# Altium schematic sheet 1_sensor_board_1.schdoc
size 353 x 259 mm
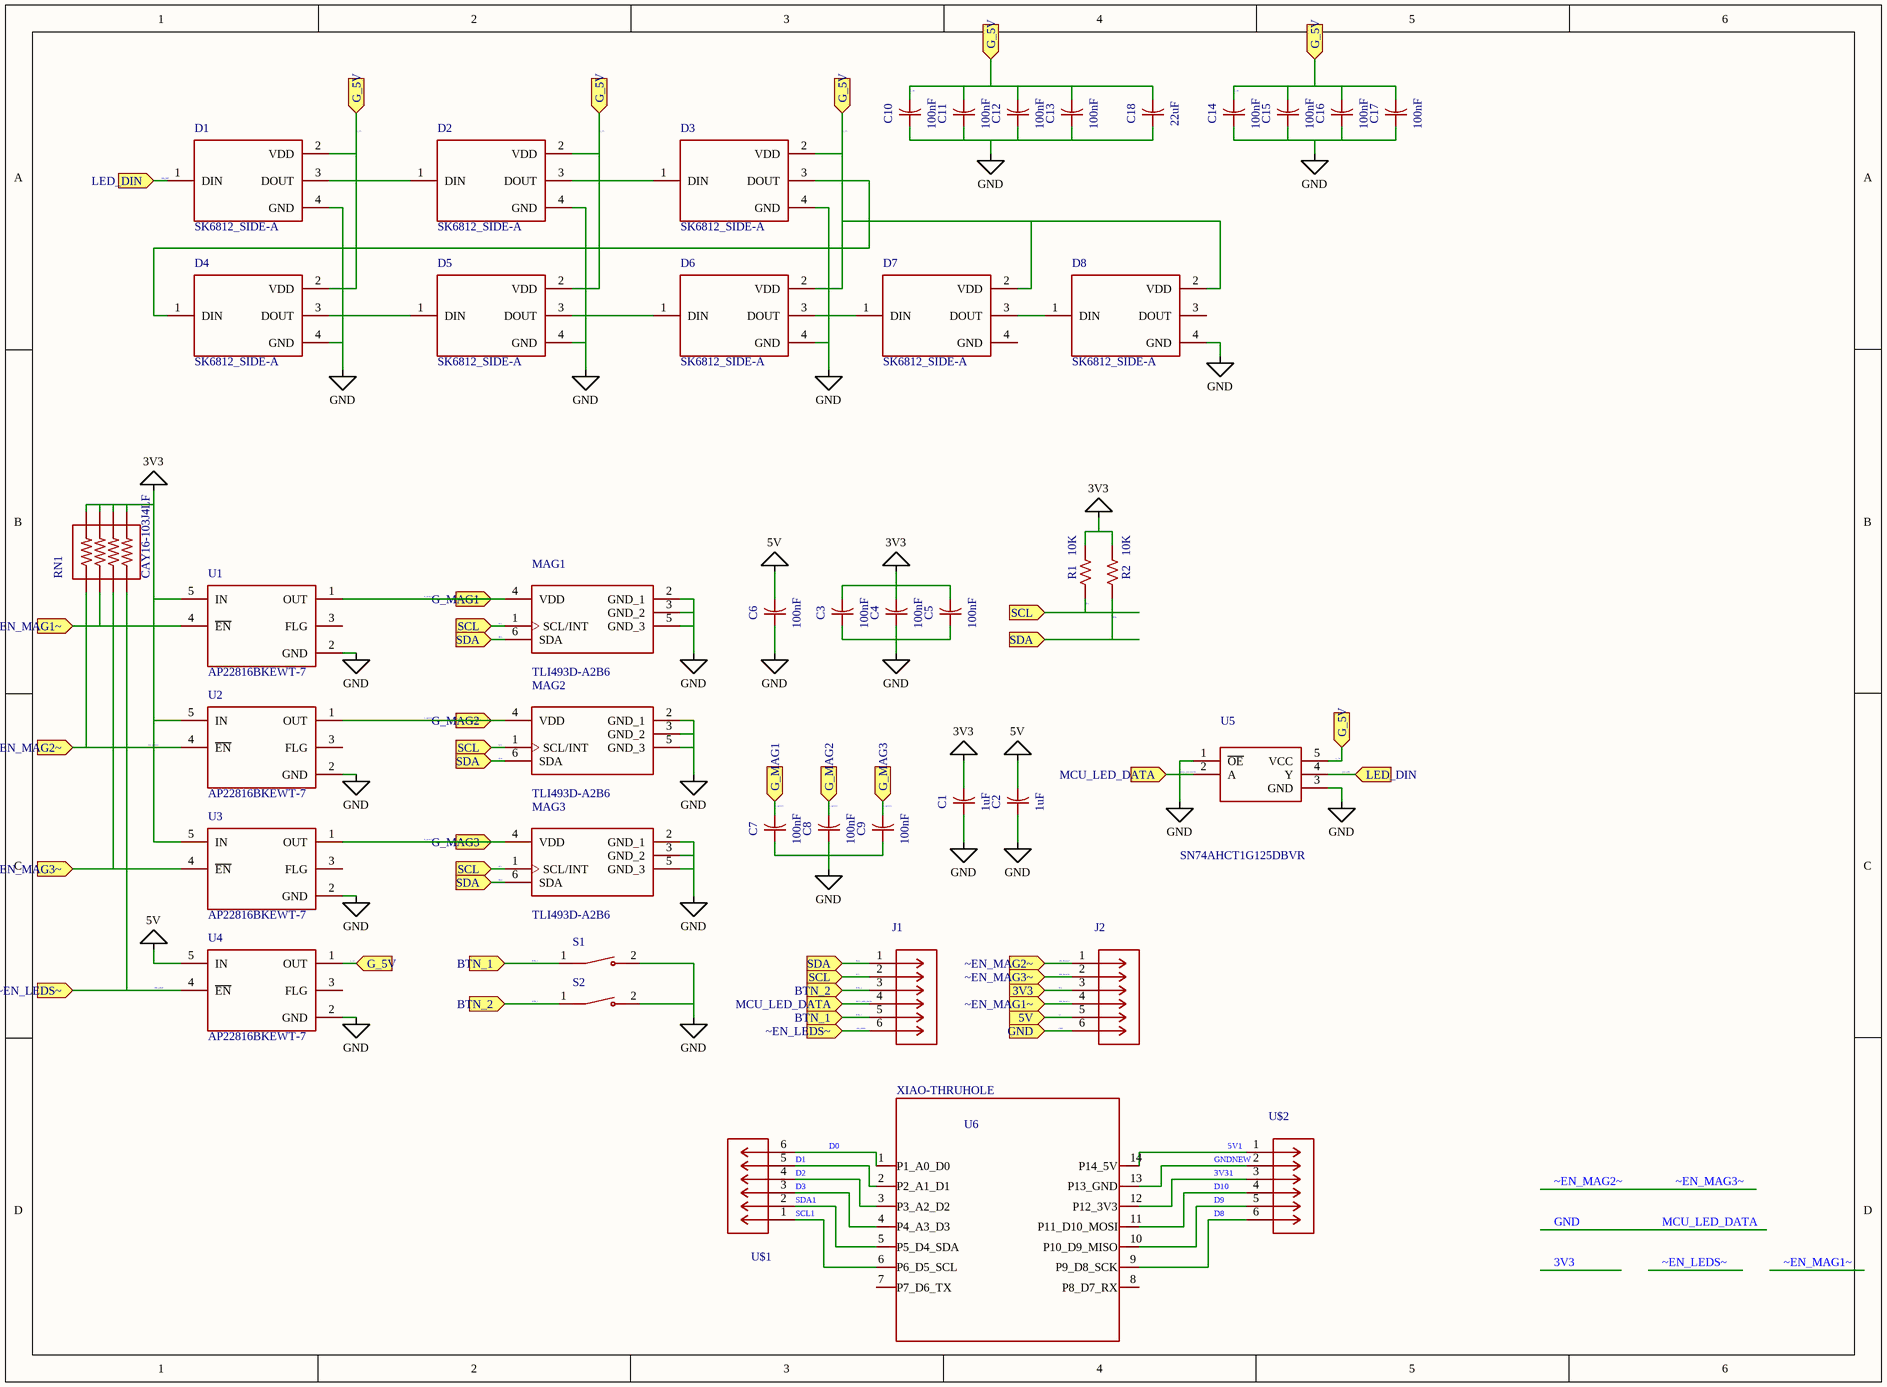
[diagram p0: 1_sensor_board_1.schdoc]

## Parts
C1  1uF  [CAPC3216X135]
C2  1uF  [CAPC3216X135]
C3  100nF  [CAPC2012X110]
C4  100nF  [CAPC2012X110]
C5  100nF  [CAPC2012X110]
C6  100nF  [CAPC2012X110]
C7  100nF  [CAPC2012X110]
C8  100nF  [CAPC2012X110]
C9  100nF  [CAPC2012X110]
C10  100nF  [CAPC2012X110]
C11  100nF  [CAPC2012X110]
C12  100nF  [CAPC2012X110]
C13  100nF  [CAPC2012X110]
C14  100nF  [CAPC2012X110]
C15  100nF  [CAPC2012X110]
C16  100nF  [CAPC2012X110]
C17  100nF  [CAPC2012X110]
C18  22uF  [CAPC3216X135]
D1  SK6812_SIDE-A  [LED_SK6812_SIDE-A]
D2  SK6812_SIDE-A  [LED_SK6812_SIDE-A]
D3  SK6812_SIDE-A  [LED_SK6812_SIDE-A]
D4  SK6812_SIDE-A  [LED_SK6812_SIDE-A]
D5  SK6812_SIDE-A  [LED_SK6812_SIDE-A]
D6  SK6812_SIDE-A  [LED_SK6812_SIDE-A]
D7  SK6812_SIDE-A  [LED_SK6812_SIDE-A]
D8  SK6812_SIDE-A  [LED_SK6812_SIDE-A]
J1  NPPN032AFCN-RCCONN3X2_NPPN032AFCN-RC_SUL  [CONN3X2_NPPN032AFCN-RC_SUL]  (value not drawn)
J2  NPPN032AFCN-RCCONN3X2_NPPN032AFCN-RC_SUL  [CONN3X2_NPPN032AFCN-RC_SUL]  (value not drawn)
MAG1  TLI493D-A2B6  [SOP95P280X110-6N-V]
MAG2  TLI493D-A2B6  [SOP95P280X110-6N-V]
MAG3  TLI493D-A2B6  [SOP95P280X110-6N-V]
R1  10K  [RESC2012X65]
R2  10K  [RESC2012X65]
RN1  CAY16-103J4LF  [RESCAF80P320X160X60-8N]
S1  TS32-7-35-BK-160-RA-SMT-TR  [SW_TS32-7-35-BK-160-RA-SMT-TR]  (value not drawn)
S2  TS32-7-35-BK-160-RA-SMT-TR  [SW_TS32-7-35-BK-160-RA-SMT-TR]  (value not drawn)
U1  AP22816BKEWT-7  [SOT95P280X100-5N]
U2  AP22816BKEWT-7  [SOT95P280X100-5N]
U3  AP22816BKEWT-7  [SOT95P280X100-5N]
U4  AP22816BKEWT-7  [SOT95P280X100-5N]
U5  SN74AHCT1G125DBVR  [SOT95P280X145-5N]
U6  XIAO-THRUHOLE  [XIAO-GENERIC-THRUHOLE-MODULE14P-2.54-21X17.8MM]
U$1  NRPN032PAEN-RC  [CONN3X2_NRPN032PAEN-RC]  (value not drawn)
U$2  NRPN032PAEN-RC  [CONN3X2_NRPN032PAEN-RC]  (value not drawn)

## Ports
3V3 (in), 5V (in), BTN_1 (in), BTN_2 (in), G_5V (in), G_MAG1 (in), G_MAG2 (in), G_MAG3 (in), GND (in), LED_DIN (in), MCU_LED_DATA (in), SCL (in), SDA (in), ~EN_LEDS~ (in), ~EN_MAG1~ (in), ~EN_MAG2~ (in), ~EN_MAG3~ (in)

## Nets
3V3: C1.2 C3.2 C4.2 C5.2 J2.3 R1.2 R2.2 RN1.5 RN1.6 RN1.7 RN1.8 U1.5(IN) U2.5(IN) U3.5(IN) ; port 3V3
5V: C2.2 C6.2 J2.5 U4.5(IN) ; port 5V
GND: C1.1 C2.1 C3.1 C4.1 C5.1 C6.1 C7.1 C8.1 C9.1 C10.1 C11.1 C12.1 C13.1 C14.1 C15.1 C16.1 C17.1 C18.1 D1.4(GND) D2.4(GND) D3.4(GND) D4.4(GND) D5.4(GND) D6.4(GND) D8.4(GND) J1.4 J2.6 MAG1.2(GND_1) MAG1.3(GND_2) MAG1.5(GND_3) MAG2.2(GND_1) MAG2.3(GND_2) MAG2.5(GND_3) MAG3.2(GND_1) MAG3.3(GND_2) MAG3.5(GND_3) S1.2 S2.2 U1.2(GND) U2.2(GND) U3.2(GND) U4.2(GND) U5.1(~{OE}) U5.2(A) U5.3(GND) ; port GND, port MCU_LED_DATA  [also labelled MCU_LED_DATA]
3V31: U6.12(P12_3V3) U$2.3
5V1: U6.14(P14_5V) U$2.1
BTN_1: J1.5 S1.1 ; port BTN_1
BTN_2: J1.3 S2.1 ; port BTN_2
D0: U6.1(P1_A0_D0) U$1.6
D1: U6.2(P2_A1_D1) U$1.5
D2: U6.3(P3_A2_D2) U$1.4
D3: U6.4(P4_A3_D3) U$1.3
D8: U6.9(P9_D8_SCK) U$2.6
D9: U6.10(P10_D9_MISO) U$2.5
D10: U6.11(P11_D10_MOSI) U$2.4
G_5V: C10.2 C11.2 C12.2 C13.2 C14.2 C15.2 C16.2 C17.2 C18.2 D1.2(VDD) D2.2(VDD) D3.2(VDD) D4.2(VDD) D5.2(VDD) D6.2(VDD) D7.2(VDD) D8.2(VDD) U4.1(OUT) U5.5(VCC) ; port G_5V
G_MAG1: C7.2 MAG1.4(VDD) U1.1(OUT) ; port G_MAG1
G_MAG2: C8.2 MAG2.4(VDD) U2.1(OUT) ; port G_MAG2
G_MAG3: C9.2 MAG3.4(VDD) U3.1(OUT) ; port G_MAG3
GNDNEW: U6.13(P13_GND) U$2.2
LED_DIN: D1.1(DIN) U5.4(Y) ; port LED_DIN
SCL: J1.2 MAG1.1(SCL/INT) MAG2.1(SCL/INT) MAG3.1(SCL/INT) R1.1 ; port SCL
SCL1: U6.6(P6_D5_SCL) U$1.1
SDA: J1.1 MAG1.6(SDA) MAG2.6(SDA) MAG3.6(SDA) R2.1 ; port SDA
SDA1: U6.5(P5_D4_SDA) U$1.2
~EN_LEDS~: J1.6 J2.4 RN1.2 RN1.4 U1.4(~{EN}) U4.4(~{EN}) ; port ~EN_MAG1~, port ~EN_LEDS~  [also labelled ~EN_MAG1~]
~EN_MAG2~: J2.1 J2.2 RN1.1 RN1.3 U2.4(~{EN}) U3.4(~{EN}) ; port ~EN_MAG2~, port ~EN_MAG3~  [also labelled ~EN_MAG3~]
NetD1_3: D1.3(DOUT) D2.1(DIN)
NetD2_3: D2.3(DOUT) D3.1(DIN)
NetD3_3: D3.3(DOUT) D4.1(DIN)
NetD4_3: D4.3(DOUT) D5.1(DIN)
NetD5_3: D5.3(DOUT) D6.1(DIN)
NetD6_3: D6.3(DOUT) D7.1(DIN)
NetD7_3: D7.3(DOUT) D8.1(DIN)

Not connected (* = marked no-connect by the designer): D7 4(GND); D8 3(DOUT); U1 3(FLG); U2 3(FLG); U3 3(FLG); U4 3(FLG); U6 7(P7_D6_TX) 8(P8_D7_RX)

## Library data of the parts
C1 C2 C18 = Capacitor_C-US_CHIP-1206(3216-METRIC): TYPE: MLCC; Add into BOM: yes
C3-C17 = Capacitor_C-US_CHIP-0805(2012-METRIC): TYPE: MLCC; Add into BOM: yes
D1-D8 = SK6812_SIDE-A_SK6812_SIDE-A_: MF: Norman Electric; MP: SK6812 SIDE-A; Package1: NON-STANDARD-4 Normand Electronics; Add into BOM: yes
J1 J2 = NPPN032AFCN-RC_NPPN032AFCN-RC_CONN3X2_NPPN032AFCN-RC_SUL: MANUFACTURER_NAME: Sullins; Add into BOM: yes
MAG1-MAG3 = TLI493D-A2B6_TLI493D-A2B6_: Add into BOM: yes
R1 R2 = Resistor_R-US_CHIP-0805(2012-METRIC): Add into BOM: yes
RN1 = CAY16-103J4LF_CAY16-103J4LF_: MF: Bourns; Package1: 1206 Bourns; Add into BOM: yes
S1 S2 = TS32-7-35-BK-160-RA-SMT-TR_TS32-7-35-BK-160-RA-SMT-TR_: MANUFACTURER: Same Sky; Add into BOM: yes
U1-U4 = AP22816BKEWT-7_AP22816BKEWT-7_: MF: Diodes Zetex; Package1: None; Add into BOM: yes
U5 = SN74AHCT1G125DBVR_SN74AHCT1G125DBVR_: Add into BOM: yes
U6 = Seeed Studio XIAO Series_XIAO-THRUHOLE_: Add into BOM: yes
U$1 U$2 = NPPN032AFCN-RC_NRPN032PAEN-RC_: Add into BOM: yes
